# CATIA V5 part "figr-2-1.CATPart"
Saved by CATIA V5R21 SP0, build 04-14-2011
Part number: Figure 1-1
Description: Solid Model for Figure 1-1
Bounding box of the stored display mesh (mm): x -10 to 10, y -87.5 to 74.833, z -24.875 to 24.875
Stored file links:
  D:\CATIA V5R21 E-RESOURCES\CATIA-V5R21\catia-v5r21-prt\c02-catia-v5r21-prt\catia-v5r21-figr-2-1.CATPart
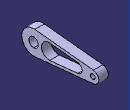
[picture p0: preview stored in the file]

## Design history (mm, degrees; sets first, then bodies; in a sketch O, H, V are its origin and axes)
Body1 (main body)
  Sketch1 on yz-plane, origin (0, 0, 0), H (0, 1, 0), V (0, 0, 1)
    construction arc A1 centre (0, 62.5) radius 25 from (24.8747, 60) to (-24.8747, 60) ccw
    point P1 (0, 62.5)
    construction arc A2 centre (0, -62.5) radius 12.5 from (-12.4373, -63.75) to (12.4373, -63.75) ccw
    point P2 (0, -62.5)
    point P3 (0, -50)
    construction line L1 (24.8747, 60) -> (12.4373, -63.75)
    construction line L2 (-24.8747, 60) -> (-12.4373, -63.75)
    construction circle A3 centre (0, 62.5) radius 10
    construction circle A4 centre (0, -62.5) radius 5
    point P8 (0, 30)
    point P9 (0, -30)
    construction line L3 (15.9198, 28.4) -> (9.9499, -31)
    construction line L4 (-9.9499, -31) -> (-15.9198, 28.4)
    construction arc A5 centre (0, -30) radius 10 from (9.9499, -31) to (-9.9499, -31) cw
    construction arc A6 centre (0, 30) radius 16 from (-15.9198, 28.4) to (15.9198, 28.4) cw
    construction line L5 through (0, 0) direction (-1, 0)
    construction line L6 through (0, 0) direction (0, 1)
    point P14 (0, 0)
    arc A7 centre (-30, 0) radius 16 from (-28.4, -15.9198) to (-28.4, 15.9198) cw
    arc A8 centre (30, 0) radius 10 from (31, 9.9499) to (31, -9.9499) cw
    line L7 (31, -9.9499) -> (-28.4, -15.9198)
    line L8 (-28.4, 15.9198) -> (31, 9.9499)
    circle A9 centre (62.5, 0) radius 5
    circle A10 centre (-62.5, 0) radius 10
    line L9 (-60, -24.8747) -> (63.75, -12.4373)
    line L10 (-60, 24.8747) -> (63.75, 12.4373)
    arc A11 centre (62.5, 0) radius 12.5 from (63.75, -12.4373) to (63.75, 12.4373) ccw
    arc A12 centre (-62.5, 0) radius 25 from (-60, 24.8747) to (-60, -24.8747) ccw
    point P27 (50, 0)
    radius A1 = 25
    radius A2 = 12.5
    radius A3 = 10
    radius A4 = 5
    distance P1 P2 = 125
    distance P1 H = 62.5 {= Sketch1.distance(P1 P2) /2}
    distance P8 H = 30
    distance P8 P9 = 60
    radius A5 = 10
    coincidence: P1 V, P2 V, A2 P3, P3 V, P8 V
    tangency: L1 A1, L1 A2, L2 A1, L2 A2, A6 L3, A6 L4, L3 A5, A5 L4
    parallelism: L3 L1, L4 L2
  Pad1: profile Sketch1, direction (1, 0, 0), length 10, mirrored extent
